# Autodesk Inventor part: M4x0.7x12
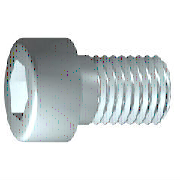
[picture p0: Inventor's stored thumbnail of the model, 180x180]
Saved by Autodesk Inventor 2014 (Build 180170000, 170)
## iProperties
IsCustomPart: 0
Created: 2016-05
Part Number: M4x0.7x12
Material: 강, 연강
Description: 6각머리 태핑 나사
Document SubType Name: Modeling
Standard: KS B 1003
Designer: mduedu
Standards Organization: KS
Language: ko-KR
Size Designation: M 4 x 12
Categories: <MemberInstance><Categories><Category DisplayName="조임쇠" InternalName="e4da775c-781d-43d5-af7c-5136215cf5a6" Mnemonic="FSTN"><Category DisplayName="볼트" InternalN
Density: 1 g/cm^3
Appearance: Honed - Dark Gray
Author: mduedu
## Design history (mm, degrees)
sketch "스케치1"
  geometry: L1 (-1, 0)-(12, 0); L2 (12, 0)-(12, 2); L3 (12, 2)-(1.75, 2); L4 (1.75, 2)-(1.32, 2); L5 (1.32, 2)-(0, 2); L6 (0, 2)-(0, 3.5); L7 (0, 3.5)-(-4, 3.5); L8 (-4, 3.5)-(-4, 1.732); L9 (-4, 1.732)-(-2, 1.732); L10 (-2, 1.732)-(-1, 0); L11 (-7.2, 0)-(15.2, 0) reference; L12 (0, -0.7)-(0, 4.2) reference; L13 (1.75, 2)-(0, 2)
  constraints: 22 end point, 6 parallel, 2 collinear, 2 perpendicular, 1 horizontal, 1 point on line
  dimensions: "d1" = 10.25 distance from line of L3.end L2 (= GEL); "d2" = 0.42952 distance of L4.end L3.end (computed from GAL); "d3" = 4 distance between parallel lines of L8 L6 (= KOH); "d4" = 2 distance of L8.end L9.end (= INTI); "d5" = 60 deg angle of L10 L1; "d6" = 4 diameter of L3 L1 (= GD); "d7" = 4 diameter of L5 L1 (= BDM); "d8" = 3.4641 diameter of L9 L1 (= 1.1547 x SW); "d9" = 7 diameter of L7 L1 (= KOD); "d26" = 12 distance between parallel lines of L12 L2 (= NLG)
revolve "본체" sketch "스케치1" stored, may be unused: angle "d10" = 90 deg
sketch "스케치2"
  geometry: L1 (0, -4.9)-(0, 4.9) reference; L2 (-4.9, 0)-(4.9, 0) reference; L3 (1.732, 0)-(0.866, -1.5); L4 (0.866, -1.5)-(-0.866, -1.5); L5 (-0.866, -1.5)-(-1.732, 0); L6 (-1.732, 0)-(-0.866, 1.5); L7 (-0.866, 1.5)-(0.866, 1.5); L8 (0.866, 1.5)-(1.732, 0); 2 further points
  constraints: 12 end point, 1 coincident, 1 horizontal alignment, 1 point on line, 12 other
extrude "슬롯" join sketch "스케치2" stored distance "d11" = 10; taper "d12" = 0 deg
workplane "Work Plane1"
fillet "Fillet2" dims "d30" = 0.1 (= R)
body "Solid1"
fillet "모깎기1" dims "d17" = 0.4 (= RR)
feature "스레드" dims "d13" = 10.25 (= GEL), "d14" = 0
chamfer "모따기1" distance "d15" = 0.42941 (= -0.5 x SPD + 0.5 x GD); stored, may be unused: second distance "d16" = 0.42941 (= GUL), angle "d27" = 45 deg
other parameters: "GD" = 4 (= NND) [user parameter; used in 2 equation terms], "NLG" = 12 [user parameter; used in 1 equation term], "GEL" = 10.25 [user parameter; used in 2 equation terms], "KOD" = 7 [user parameter; used in 1 equation term], "KOH" = 4 [user parameter; used in 1 equation term], "INTI" = 2 [user parameter; used in 1 equation term], "GAL" = 0.42941 (= 0.61345 x PTC) [user parameter; used in 1 equation term], "GUL" = 0.42941 (= 0.61345 x PTC) [user parameter; used in 1 equation term], "BDM" = 4 (= NND) [user parameter; used in 1 equation term], "SW" = 3 [user parameter; used in 2 equation terms], "RR" = 0.4 [user parameter; used in 1 equation term], "SPD" = 3.14117 (= NND - 1.2269 x PTC) [user parameter; used in 1 equation term], "d19" = 0, "d28" = 0, "d29" = 0, "R" = 0.1 [user parameter; used in 1 equation term], "PHH" = 0.2 [user parameter], "GD1" = 3.14117 (= THREADDIA - 1.2269 x PTC) [user parameter], "THREADDIA" = 4 [user parameter; used in 1 equation term], "FAWI" = 45 deg [user parameter], "TPU" = 14.28571 (computed from PTC) [user parameter], "PTC" = 0.7 [user parameter; used in 5 equation terms], "NND" = 4 [user parameter; used in 3 equation terms], "TOA" = 30 deg [user parameter], "E0" = 3.465 (= 1.155 x SW) [user parameter]
